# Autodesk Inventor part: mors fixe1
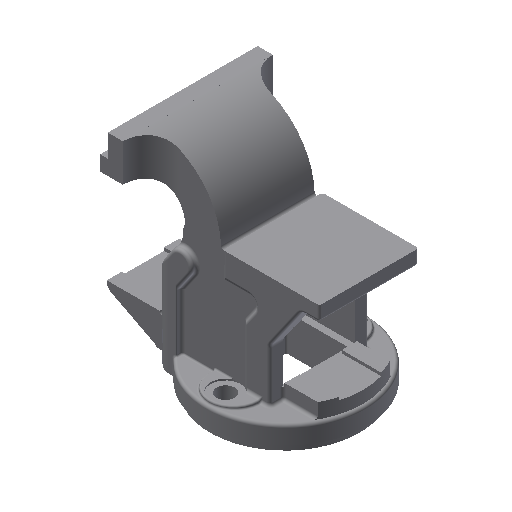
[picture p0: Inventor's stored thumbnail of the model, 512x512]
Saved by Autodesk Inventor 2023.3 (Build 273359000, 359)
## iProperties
Created: 2001-06
Part Number: mors fixe1
Material: Générique
Document SubType Name: Modélisation
Designer: Administrateur
Density: 1 g/cm^3
Appearance: Par défaut
Control State: 0
Master: False
Checked Out: False
Shininess: 21.0
Length Units: 11269
Angle Units: 11279
Time Units: 11290
Mass Units: 11283
Length Display Precision: 3
Angle Display Precision: 2
Density: 0.0
Volumn: 0.0
Area: 0.0
PropertySet Name: Model Information
Author: Administrateur
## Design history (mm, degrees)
sketch "Esquisse1"
  geometry: C1 r 53 at (19.675, 0)
  constraints: 1 centre point
  dimensions: "d0" = 106 diameter of C1
extrude "Extrusion1" new body sketch "Esquisse1" distance "d1" = 12; taper "d2" = 0 deg
fillet "Congé1" dims "d3" = 2
sketch "Esquisse2"
  geometry: C1 r 49.5 at (-0.933, -1.821)
  constraints: 1 centre point
  dimensions: "d4" = 99 diameter of C1
extrude "Extrusion2" join sketch "Esquisse2" distance "d5" = 4; taper "d6" = 0 deg
sketch "Esquisse3"
  geometry: C1 r 51 at (0, 0) reference; C2 r 16.5 at (0, 34.5); C3 r 16.5 at (0, -34.5); A1 r 34.5 centre (0, 0) between (0, 34.5) and (0, -34.5)
  constraints: 3 centre point, 2 point on circle, 1 coincident
  dimensions: "d7" = 69 diameter of A1; "d8" = 33 diameter of C3; "d9" = 33 diameter of C2
extrude "Extrusion3" join sketch "Esquisse3" distance "d10" = 2; taper "d11" = 0 deg
sketch "Esquisse5"
  geometry: L1 (54, 24)-(54, -24); L2 (45, -24)-(-95, -24); L3 (-95, -24)-(-95, 24); L4 (-95, 24)-(45, 24); C1 r 53 at (0, 0); A1 r 51 centre (0, 0) between (45, -24) and (45, 24) reference; A2 r 52 centre (0, 0) between (46.13, 24) and (-46.13, -24); 2 further points
  constraints: 8 end point, 4 point on circle, 2 centre point, 2 coincident, 2 parallel, 1 horizontal, 1 perpendicular, 1 point on line
  dimensions: "d22" = 104 diameter of A2; "d23" = 48 distance of L1.start L1.end; "d24" = 24 distance from line of L2 A1.centre; "d25" = 149 distance of L3.end L1.start; "d26" = 54 distance from line of L1 A1.centre; "d27" = 106 diameter of C1
extrude "Extrusion4" join sketch "Esquisse5" distance "d28" = 10; taper "d29" = 0 deg
sketch "Esquisse6"
  geometry: L1 (95, -24)-(45, -24) reference; L2 (95, 24)-(95, -24) reference; L3 (45, 24)-(95, 24) reference; A1 r 51 centre (0, 0) between (45, -24) and (45, 24) reference
extrude "Extrusion5" join sketch "Esquisse6" distance "d30" = 10; taper "d31" = 0 deg
sketch "Esquisse7"
  geometry: L1 (-107.728, -10)-(-107.728, 10) reference; L2 (-107.728, -10)-(-59.983, -10) reference; L3 (-59.983, -10)-(-76.775, -10); L4 (-107.728, 5.977)-(-76.775, -10); L5 (-108.465, -10)-(-107.728, 5.977)
  constraints: 6 end point, 3 point on line
extrude "Extrusion6" cut sketch "Esquisse7" extent not by distance; stored distance "d32" = 10; taper "d33" = 0 deg
fillet "Congé2" dims "d34" = 5
fillet "Congé3" dims "d35" = 5
sketch "Esquisse8"
  geometry: L1 (-95, -24)-(-95, 24) reference; L2 (-95, -14)-(56.507, -14); L3 (56.507, -14)-(56.507, 14); L4 (56.507, 14)-(-95, 14); L5 (-95, 14)-(-95, -14); A1 r 51 centre (0, 0) between (45, -24) and (45, 24) reference
  constraints: 8 end point, 2 parallel, 1 horizontal, 1 perpendicular, 1 point on line
  dimensions: "d36" = 28 distance of L4.end L2.start; "d37" = 14 distance from line of L4 A1.centre
extrude "Extrusion7" cut sketch "Esquisse8" distance "d38" = 2; taper "d39" = 0 deg
sketch "Esquisse9"
  geometry: L1 (45, -24)-(-95, -24) reference; L2 (-60, -24)-(30, -24); L3 (30, -24)-(30, 24); L4 (30, 24)-(-60, 24); L5 (-60, 24)-(-60, -24); A1 r 51 centre (0, 0) between (49.041, -14) and (49.041, 14) reference
  constraints: 8 end point, 2 parallel, 1 horizontal, 1 perpendicular, 1 point on line
  dimensions: "d40" = 90 distance of L3.end L4.end; "d41" = 48 distance of L2.end L3.end; "d42" = 30 distance from line of A1.centre L3
extrude "Extrusion8" cut sketch "Esquisse9" distance "d43" = 2; taper "d44" = 0 deg
sketch "Esquisse12"
  geometry: 1 further point
hole "Perçage2" sketch "Esquisse12" at (0, 40.133) diameter "d46" = 12; stored, may be unused: countersink angle "d50" = 60 deg, drill point angle "d52" = 118 deg; dims "d47" = 6, "d48" = 20, "d49" = 1, "d51" = 8
pattern_circular "Réseau circulaire2" dims angle "d55" = 360 deg
sketch "Esquisse13"
  geometry: L1 (75, 8)-(-15, 8) reference; L2 (32.272, 0)-(0, 0) reference; L3 (32.272, 2)-(32.272, 0) reference; L4 (57.728, 2)-(32.272, 2) reference; L5 (57.728, 0)-(57.728, 2) reference; L6 (90, 0)-(57.728, 0) reference; L7 (90, 10)-(75, 10) reference; L8 (67, 0)-(67, 35); L9 (67, 35)-(88, 65); L10 (88, 65)-(0, 65); L11 (0, 65)-(0, 0)
  constraints: 8 end point, 3 perpendicular, 1 point on line
  dimensions: "d56" = 35 distance of L8.start L8.end; "d57" = 88 distance of L9.end L10.end; "d58" = 30 distance from line of L8.end L10; "d59" = 21 horizontal distance of L9.end L8.end
extrude "Extrusion9" join sketch "Esquisse13" distance "d60" = 7; taper "d61" = 0 deg
sketch "Esquisse14"
  geometry: L1 (67, -8)-(0, -8) reference; L2 (0, -65)-(0, -8) reference; L3 (88, -65)-(0, -65) reference; L4 (67, -35)-(88, -65) reference; L5 (67, -8)-(67, -35) reference
extrude "Extrusion10" join sketch "Esquisse14" distance "d62" = 55; taper "d63" = 0 deg
sketch "Esquisse15"
  geometry: L1 (67, 0)-(0, 0) reference; L2 (67, 0)-(67, 7) reference; L3 (67, 7)-(0, 7) reference; L4 (0, 0)-(0, 7) reference
extrude "Extrusion11" join sketch "Esquisse15" distance "d64" = 10; taper "d65" = 0 deg
sketch "Esquisse16"
  geometry: L1 (88, 62)-(88, 0) reference; L2 (88, 62)-(0, 62) reference; L3 (36, 62)-(100, 62); L4 (100, 62)-(100, 0); L5 (100, 0)-(36, 0); L6 (36, 0)-(36, 62)
  constraints: 8 end point, 2 parallel, 1 horizontal, 1 perpendicular, 1 point on line
  dimensions: "d66" = 64 distance of L3.start L3.end; "d67" = 62 distance of L3.end L4.end; "d68" = 12 distance between parallel lines of L4 L1
extrude "Extrusion12" join sketch "Esquisse16" distance "d69" = 10; taper "d70" = 0 deg
sketch "Esquisse17"
  geometry: L1 (61.125, 0)-(61.125, 2) reference; L2 (67, 0)-(61.125, 0) reference; L3 (67, 35)-(67, 0) reference; L4 (88, 65)-(67, 35) reference; L5 (88, 65)-(100, 65) reference; L6 (100, 65)-(100, 75) reference; L7 (100, 75)-(36, 75) reference; L8 (61.125, 2)-(49.074, 2) reference; L9 (36, 75)-(36, 58); L10 (36, 58)-(52.746, 58); L11 (56.842, 50.133)-(50.362, 40.875); L12 (50, 39.728)-(50, 2); A1 r 5 centre (52.746, 53) between (56.842, 50.133) and (52.746, 58); A2 r 2 centre (52, 39.728) between (50.362, 40.875) and (50, 39.728); A3 r 2 centre (52, 39.728) between (50.362, 40.875) and (50, 39.728); 2 further points
  constraints: 8 end point, 7 point on line, 6 point on circle, 6 tangent, 3 centre point, 3 perpendicular, 1 parallel
  dimensions: "d71" = 17 distance of L7.end L9.end; "d72" = 17 distance between parallel lines of L4 L11; "d73" = 17 distance between parallel lines of L12 L3; "d84" = 5 radius of A1; "d85" = 2 radius of A2; "d86" = 2 radius of A3
extrude "Extrusion13" join sketch "Esquisse17" distance "d74" = 2; taper "d75" = 0 deg
fillet "Congé4" dims "d76" = 2
fillet "Congé5" dims "d77" = 2
fillet "Congé7" dims "d79" = 5
fillet "Congé8" dims "d80" = 5
fillet "Congé11" dims "d83" = 1.5
sketch "Esquisse18"
  geometry: L1 (67, 0)-(67, -33.424) reference; L2 (61.125, 0)-(67, 0) reference; L3 (61.125, -2)-(61.125, 0) reference; L4 (49.074, -2)-(61.125, -2) reference; L5 (36, -65)-(36, -75) reference; L6 (36, -75)-(100, -75) reference; L7 (100, -65)-(100, -75) reference; L8 (100, -65)-(90.603, -65) reference; L9 (67.904, -36.291)-(86.507, -62.867) reference; L10 (36, -65)-(36, -58); L11 (36, -58)-(52.746, -58); L12 (56.842, -50.133)-(50, -40.359); L13 (50, -40.359)-(50, -2); A1 r 5 centre (90.603, -60) between (86.507, -62.867) and (90.603, -65) reference; A2 r 5 centre (72, -33.424) between (67, -33.424) and (67.904, -36.291) reference; A3 r 5 centre (52.746, -53) between (52.746, -58) and (56.842, -50.133)
  constraints: 8 end point, 2 parallel, 2 perpendicular, 2 point on circle, 2 tangent, 1 centre point, 1 point on line
  dimensions: "d87" = 5 radius of A3; "d88" = 17 distance between parallel lines of L11 L6; "d89" = 17 distance between parallel lines of L12 L9; "d90" = 17 distance between parallel lines of L13 L1
extrude "Extrusion14" join sketch "Esquisse18" distance "d91" = 2; taper "d92" = 0 deg
sketch "Esquisse23"
  geometry: L1 (62.833, -24)-(49.109, -24) reference; L2 (62.833, 24)-(62.833, -24) reference; L3 (47.255, 24)-(62.833, 24) reference; A1 r 9 centre (41.261, -28.406) between (49.109, -24) and (48.01, -22.451) reference; A2 r 53 centre (0, 0) between (48.01, -22.451) and (47.255, 24) reference
extrude "Extrusion18" join sketch "Esquisse23" distance "d103" = 2; taper "d104" = 0 deg
fillet "Congé14" dims "d105" = 2
sketch "Esquisse32"
  geometry: L1 (0, -7)-(65, -7) reference; L2 (65, 55)-(65, -7) reference; L3 (65, 55)-(-2, 55) reference; L4 (-2, 55)-(-2, 52) reference; L5 (8, 48)-(0, 48) reference; L6 (8, 0)-(8, 48) reference; L7 (0, 0)-(8, 0) reference; L8 (0, 0)-(0, -7) reference
  constraints: 1 other
extrude "Extrusion27" join sketch "Esquisse32" distance "d126" = 8; taper "d127" = 0 deg
sketch "Esquisse33"
  geometry: L1 (55.642, 50.972)-(49.162, 41.715) reference; L2 (-8, 65)-(34.536, 65) reference; L3 (-8, 65)-(-8, 0) reference; L4 (-8, 65)-(-8, 47.66); L5 (7.378, 65)-(-8, 43.032); L6 (52, 39.728)-(58.48, 48.986) reference
  constraints: 4 end point, 3 point on line, 2 parallel
extrude "Extrusion28" cut sketch "Esquisse33" extent not by distance; stored distance "d128" = 10; taper "d129" = 0 deg
sketch "Esquisse34"
  geometry: L1 (-8, -43.032)-(7.378, -65) reference; L2 (56.842, -50.133)-(50, -40.359) reference; L3 (2.012, 2)-(-8, 2) reference; L4 (-8, 2)-(-8, -43.032) reference; L5 (2, 2)-(2, -31.161); L6 (2, -31.161)-(16.636, -52.07); A1 r 7.5 centre (10.492, -56.371) between (4.348, -60.671) and (16.636, -52.07)
  constraints: 4 end point, 2 parallel, 2 point on circle, 2 point on line, 1 centre point, 1 tangent
  dimensions: "d130" = 10 distance between parallel lines of L4 L5; "d131" = 15 distance between parallel lines of L1 L6
extrude "Extrusion29" join sketch "Esquisse34" distance "d133" = 4; taper "d134" = 0 deg
sketch "Esquisse35"
  geometry: L1 (67, 4)-(75, 4) reference; L2 (75, 4)-(75, 11) reference; L3 (75, 11)-(65, 11) reference; L4 (65, 7)-(65, 11) reference; L5 (64.988, 7)-(65, 7) reference; A1 r 53 centre (22, -24) between (67, 4) and (64.988, 7) reference
extrude "Extrusion30" join sketch "Esquisse35" distance "d135" = 10; taper "d136" = 0 deg
sketch "Esquisse36"
  geometry: L1 (0, 0)-(8, 0) reference; L2 (8, 10)-(8, 0) reference; L3 (8, 10)-(0, 10) reference; L4 (0, 10)-(0, 0) reference
extrude "Extrusion31" join sketch "Esquisse36" stored distance "d137" = 10; taper "d138" = 0 deg
sketch "Esquisse39"
  geometry: L1 (-4.503, -7)-(8, -7) reference; L2 (8, -7)-(8, 0) reference; L3 (0, 0)-(8, 0) reference; A1 r 51 centre (-45, 24) between (-4.503, -7) and (0, 0) reference
extrude "Extrusion33" join sketch "Esquisse39" distance "d141" = 12; taper "d142" = 0 deg
sketch "Esquisse40"
  geometry: L1 (49.109, -24)-(47.255, -24) reference; A1 r 9 centre (41.261, -28.406) between (49.109, -24) and (48.01, -22.451) reference; A2 r 53 centre (0, 0) between (47.255, -24) and (48.01, -22.451) reference
extrude "Extrusion34" join sketch "Esquisse40" distance "d143" = 2; taper "d144" = 0 deg
sketch "Esquisse41"
  geometry: L1 (7.378, 65)-(-8, 43.032) reference; L2 (-8, 43.032)-(-8, -12) reference; L3 (-8, -12)-(2.012, -12) reference; L4 (2.012, -2)-(2.012, -12) reference; L5 (7.378, 65)-(34.536, 65) reference; L6 (-8, -12)-(-8, 43.032); L7 (13.877, 61.207)-(13.877, 61.207); L8 (15.721, 50.761)-(2.012, 31.177); L9 (2.012, 31.177)-(2.012, -12); L10 (3.432, 59.363)-(-8, 43.032); L11 (-8, -12)-(2.012, -12); A1 r 7.5 centre (9.576, 55.062) between (15.721, 50.761) and (13.877, 61.207); A2 r 7.5 centre (9.576, 55.062) between (13.877, 61.207) and (3.432, 59.363)
  constraints: 12 end point, 4 point on circle, 4 tangent, 3 collinear, 2 centre point, 2 perpendicular, 1 parallel
  dimensions: "d149" = 15 distance between parallel lines of L1 L8; "d201" = 7.5 radius of A2; "d202" = 7.5 radius of A1
extrude "Extrusion35" join sketch "Esquisse41" distance "d147" = 4; taper "d148" = 0 deg
sketch "Esquisse44"
  geometry: L1 (8, 0)-(0, 0) reference; L2 (0, 0)-(0, -4) reference; L3 (5.745, -4)-(0, -4) reference; A1 r 53 centre (53, -28) between (8, 0) and (5.745, -4) reference
extrude "Extrusion36" join sketch "Esquisse44" stored distance "d154" = 4; taper "d155" = 0 deg
fillet "Congé35" dims "d173" = 10
sketch "Esquisse47"
  geometry: L1 (43.161, 4)-(0, 4) reference; L2 (0, 0)-(0, 4) reference; L3 (43.161, 0)-(0, 0) reference; L4 (43.161, 0)-(43.161, 4) reference
extrude "Extrusion39" join sketch "Esquisse47" distance "d174" = 5; taper "d175" = 0 deg
sketch "Esquisse48"
  geometry: L1 (0, -4)-(43.177, -4) reference; L2 (43.177, 0)-(43.177, -4) reference; L3 (33.177, 0)-(43.177, 0) reference; L4 (0, 0)-(33.177, 0) reference; L5 (0, 0)-(0, -4) reference
extrude "Extrusion40" join sketch "Esquisse48" distance "d176" = 5; taper "d177" = 0 deg
fillet "Congé36" dims "d182" = 2
fillet "Congé37" dims "d183" = 2
fillet "Congé38" dims "d184" = 2
fillet "Congé39" dims "d185" = 0.5
fillet "Congé40" dims "d186" = 2
fillet "Congé41" dims "d187" = 0.5
fillet "Congé42" dims "d188" = 2
fillet "Congé43" dims "d189" = 2
sketch "Esquisse51"
  geometry: L1 (5, 0.5)-(5, 2) reference; L2 (0, 4)-(7, 4) reference; L3 (0, 4)-(0, 0) reference; L4 (0, 0)-(4.5, 0) reference; A1 r 0.5 centre (4.5, 0.5) between (4.5, 0) and (5, 0.5) reference; A2 r 2 centre (7, 2) between (7, 4) and (5, 2) reference
extrude "Extrusion43" join sketch "Esquisse51" stored distance "d194" = 5; taper "d195" = 0 deg
sketch "Esquisse52"
  geometry: L1 (0, 4)-(4.5, 4) reference; L2 (0, 0)-(0, 4) reference; L3 (7, 0)-(0, 0) reference; L4 (5, 2)-(5, 3.5) reference; A1 r 0.5 centre (4.5, 3.5) between (5, 3.5) and (4.5, 4) reference; A2 r 2 centre (7, 2) between (5, 2) and (7, 0) reference
extrude "Extrusion44" join sketch "Esquisse52" stored distance "d196" = 5; taper "d197" = 0 deg
fillet "Congé50" dims "d203" = 2
fillet "Congé51" dims "d204" = 2
fillet "Congé52" dims "d205" = 2
sketch "Esquisse53"
  geometry: L1 (8, 49)-(8, -1) reference; L2 (8, 48)-(58, 48); L3 (58, 48)-(58, 0); L4 (58, 0)-(8, 0); L5 (8, 0)-(8, 48); L6 (75, 57)-(58, 57) reference
  constraints: 8 end point, 2 parallel, 1 horizontal, 1 perpendicular, 1 point on line
  dimensions: "d206" = 48 distance of L2.end L3.end; "d207" = 9 distance between parallel lines of L6 L2; "d208" = 50 distance of L2.start L2.end
extrude "Extrusion45" cut sketch "Esquisse53" distance "d209" = 91; taper "d210" = 0 deg
sketch "Esquisse55"
  geometry: L1 (10, 10)-(10, 0) reference; L2 (8, 10)-(10, 10) reference; L3 (8, 10)-(8, 0) reference; L4 (10, 0)-(8, 0) reference
extrude "Extrusion46" join sketch "Esquisse55" distance "d211" = 15; taper "d212" = 0 deg
sketch "Esquisse56"
  geometry: L1 (10, 48)-(10, 38) reference; L2 (8, 48)-(10, 48) reference; L3 (8, 48)-(8, 38) reference; L4 (10, 38)-(8, 38) reference
extrude "Extrusion47" join sketch "Esquisse56" distance "d213" = 15; taper "d214" = 0 deg
sketch "Esquisse57"
  geometry: L1 (80.522, 0)-(80.522, -48) reference; L2 (80.522, -48)-(0, -48) reference; L3 (80.522, -14)-(-14.478, -14); L4 (-14.478, -14)-(-14.478, -34); L5 (-14.478, -34)-(80.522, -34); L6 (80.522, -34)-(80.522, -14)
  constraints: 8 end point, 2 parallel, 1 horizontal, 1 perpendicular, 1 point on line
  dimensions: "d215" = 20 distance of L5.end L3.start; "d216" = 14 distance between parallel lines of L2 L5; "d217" = 95 distance of L4.end L5.end
extrude "Extrusion48" cut sketch "Esquisse57" distance "d218" = 6; taper "d219" = 0 deg
fillet "Congé53" dims "d220" = 2
sketch "Esquisse58"
  geometry: L1 (80.522, 0)-(0, 0) reference; L2 (80.522, 14)-(80.522, 0) reference; L3 (62.261, 0)-(18.261, 0); L4 (18.261, 0)-(18.261, 48); L5 (18.261, 48)-(62.261, 48); L6 (62.261, 48)-(62.261, 0)
  constraints: 8 end point, 2 parallel, 1 horizontal, 1 perpendicular, 1 point on line
  dimensions: "d221" = 48 distance of L5.end L3.start; "d222" = 44 distance of L3.start L3.end; "d223" = 18.2615 distance between parallel lines of L6 L2
extrude "Extrusion49" cut sketch "Esquisse58" distance "d224" = 8; taper "d225" = 0 deg
fillet "Congé54" dims "d226" = 5
fillet "Congé55" dims "d227" = 2
fillet "Congé56" dims "d228" = 5
fillet "Congé57" dims "d229" = 5
fillet "Congé58" dims "d230" = 2
fillet "Congé59" dims "d231" = 2
sketch "Esquisse59"
  geometry: L1 (0, 0)-(28.622, 0); L2 (28.622, 0)-(28.622, 62); L3 (28.622, 62)-(0, 62); L4 (0, 62)-(0, 0)
  constraints: 8 end point, 2 parallel, 1 horizontal, 1 perpendicular
extrude "Extrusion50" join sketch "Esquisse59" distance "d232" = 8; taper "d233" = 0 deg
fillet "Congé60" dims "d234" = 2
fillet "Congé61" dims "d235" = 2
fillet "Congé62" dims "d236" = 2
fillet "Congé63" dims "d237" = 2
fillet "Congé64" dims "d238" = 2
fillet "Congé65" dims "d239" = 10
fillet "Congé66" dims "d240" = 2
fillet "Congé67" dims "d241" = 2
fillet "Congé68" dims "d242" = 2
fillet "Congé69" dims "d243" = 1
fillet "Congé70" dims "d244" = 2
fillet "Congé71" dims "d245" = 2
fillet "Congé72" dims "d246" = 1
fillet "Congé73" dims "d247" = 1
fillet "Congé74" dims "d248" = 2
fillet "Congé75" dims "d249" = 2
fillet "Congé76" dims "d250" = 2
fillet "Congé77" dims "d251" = 1
fillet "Congé78" dims "d252" = 2
fillet "Congé79" dims "d253" = 2
fillet "Congé80" dims "d254" = 2
fillet "Congé81" dims "d255" = 2
fillet "Congé82" dims "d256" = 2
fillet "Congé83" dims "d257" = 1
fillet "Congé84" dims "d258" = 1
fillet "Congé85" dims "d259" = 1
sketch "Esquisse60"
  geometry: L1 (91, 49.857)-(75.904, 28.291) reference; L2 (28.36, 50)-(72.739, 50) reference; L3 (91, 50)-(83.452, 39.074); L4 (91, 50)-(50.55, 50); L5 (91, 50)-(48.029, 50); L6 (72.739, 38)-(82.7, 38); L7 (72.739, 38)-(72.739, 50); L8 (91, 50)-(82.7, 38)
  constraints: 12 end point, 3 point on line, 2 midpoint, 1 parallel, 1 perpendicular
  dimensions: "d260" = 12 distance of L6.start L7.end; "d261" = 0 distance from line of L2.end L7
extrude "Extrusion51" join sketch "Esquisse60" stored distance "d262" = 2; taper "d263" = 0 deg
sketch "Esquisse61"
  geometry: L1 (9.078, 48)-(26.739, 48) reference; L2 (0.362, 35.548)-(9.078, 48) reference; L3 (75, 25.424)-(75, 0) reference; L4 (26.739, 48)-(26.739, 36); L5 (26.739, 36)-(0, 34.401); L6 (9.078, 48)-(26.739, 48); A1 r 2 centre (2, 34.401) between (0.362, 35.548) and (0, 34.401) reference; 1 further point
  constraints: 6 end point, 2 perpendicular, 1 point on line
  dimensions: "d264" = 12 distance of L4.start L4.end; "d265" = 0 distance from line of point (26.739, 50) L4
extrude "Extrusion52" join sketch "Esquisse61" stored distance "d266" = 2; taper "d267" = 0 deg
sketch "Esquisse63"
  geometry: L1 (12, -48)-(0, -48) reference; L2 (0, 0)-(0, -48) reference; L3 (0, -47)-(20, -47); L4 (20, -47)-(20, -1); L5 (20, -1)-(0, -1); L6 (0, -1)-(0, -47)
  constraints: 8 end point, 2 parallel, 1 horizontal, 1 perpendicular, 1 point on line
  dimensions: "d272" = 46 distance of L3.end L4.end; "d273" = 20 distance of L3.start L3.end; "d274" = 1 distance between parallel lines of L3 L1
extrude "Extrusion54" cut sketch "Esquisse63" extent not by distance; stored distance "d275" = 2; taper "d276" = 0 deg
fillet "Congé86" dims "d277" = 1
fillet "Congé87" dims "d278" = 1
fillet "Congé88" dims "d279" = 1
sketch "Esquisse64"
  geometry: L1 (0, 0)-(-12, 0) reference; L2 (0, 47)-(-20, 47); L3 (-20, 47)-(-20, 1); L4 (-20, 1)-(0, 1); L5 (0, 1)-(0, 47); L6 (0, 39)-(0, 9) reference
  constraints: 8 end point, 2 parallel, 1 horizontal, 1 perpendicular
  dimensions: "d280" = 46 distance of L2.end L3.end; "d281" = 20 distance of L3.end L4.end; "d282" = 1 distance between parallel lines of L1 L4; "d285" = 0 distance between parallel lines of L5 L6
extrude "Extrusion55" cut sketch "Esquisse64" extent not by distance; stored distance "d283" = 2; taper "d284" = 0 deg
fillet "Congé89" dims "d286" = 1
sketch "Esquisse65"
  geometry: L1 (-53, 24)-(22, 24) reference; L2 (-23, 12.5)-(-53, 12.5); L3 (-53, 12.5)-(-53, -12.5); L4 (-53, -12.5)-(-23, -12.5); L5 (-23, -12.5)-(-23, 12.5)
  constraints: 8 end point, 2 parallel, 1 horizontal, 1 perpendicular
  dimensions: "d287" = 25 distance of L2.end L3.end; "d288" = 30 distance of L3.end L4.end; "d289" = 11.5 distance between parallel lines of L1 L2; "d290" = 0 distance from line of L3 L1.start
extrude "Extrusion56" join sketch "Esquisse65" distance "d291" = 2; taper "d292" = 0 deg
fillet "Congé90" dims "d293" = 2
sketch "Esquisse66"
  geometry: L1 (-53, 12.5)-(-23, 12.5) reference; L2 (-53, -12.5)-(-53, 12.5) reference; 1 further point
  dimensions: "d294" = 12.5 distance from line of L1 point (-33, 0); "d295" = 20 distance from line of L2 point (-33, 0)
hole "Perçage3" sketch "Esquisse66" at (-33, 0) diameter "d296" = 8; stored, may be unused: countersink angle "d300" = 60 deg, drill point angle "d302" = 118 deg; dims "d297" = 6, "d298" = 15, "d299" = 9, "d301" = 8
sketch "Esquisse68"
  geometry: L1 (-20.5, -21.5)-(-20.5, 21.5); L2 (-20.5, 21.5)-(20.5, 21.5); L3 (20.5, 21.5)-(20.5, -21.5); L4 (20.5, -21.5)-(-20.5, -21.5); C1 r 49.5 at (0, 0) reference
  constraints: 8 end point, 2 parallel, 1 perpendicular, 1 vertical
  dimensions: "d306" = 43 distance of L1.start L1.end; "d307" = 41 distance of L1.end L2.end; "d308" = 20.5 distance from line of C1.centre L1; "d309" = 21.5 distance from line of C1.centre L2
extrude "Extrusion58" cut sketch "Esquisse68" stored distance "d310" = 10; taper "d311" = 0 deg
fillet "Congé91" dims "d312" = 1
sketch "Esquisse69"
  geometry: L1 (2, 62)-(27.794, 62) reference; L2 (2, 0)-(2, 62) reference; L3 (2, 0)-(25.518, 0); L4 (25.518, 0)-(25.518, 62); L5 (25.518, 62)-(2, 62); L6 (2, 62)-(2, 0)
  constraints: 8 end point, 2 parallel, 1 horizontal, 1 perpendicular
  dimensions: "d313" = 23.51808 distance of L4.end L5.end; "d314" = 0 distance between parallel lines of L2 L6; "d315" = 0 distance between parallel lines of L1 L5
extrude "Extrusion59" join sketch "Esquisse69" distance "d316" = 48; taper "d317" = 0 deg
sketch "Esquisse70"
  geometry: L1 (0, 0)-(0, 62) reference; L2 (-48, 62)-(0, 62) reference; L3 (-48, 0)-(0, 0) reference; L4 (0, 62)-(-25, 62); L5 (-25, 62)-(-25, 0); L6 (-25, 0)-(0, 0); L7 (0, 0)-(0, 62)
  constraints: 8 end point, 2 parallel, 1 horizontal, 1 perpendicular, 1 point on line
  dimensions: "d318" = 25 distance of L5.end L6.end; "d319" = 0 distance between parallel lines of L1 L7; "d320" = 0 distance between parallel lines of L3 L6
extrude "Extrusion60" join sketch "Esquisse70" distance "d321" = 38; taper "d322" = 0 deg
fillet "Congé92" dims "d323" = 48
fillet "Congé93" dims "d324" = 23
sketch "Esquisse71"
  geometry: L1 (0, 62)-(0, 0) reference; L2 (-25, 62)-(0, 62) reference; L3 (-25, 0)-(-25, 62) reference; L4 (-25, -18.75)-(0, -18.75); L5 (0, -18.75)-(0, 80.75); L6 (0, 80.75)-(-25, 80.75); L7 (-25, 80.75)-(-25, -18.75)
  constraints: 8 end point, 2 parallel, 1 horizontal, 1 perpendicular, 1 point on line
  dimensions: "d325" = 0 distance between parallel lines of L1 L5; "d326" = 99.5 distance between parallel lines of L6 L4; "d328" = 18.75 distance between parallel lines of L6 L2
extrude "Extrusion61" join sketch "Esquisse71" distance "d329" = 15; taper "d330" = 0 deg
fillet "Congé94" dims "d331" = 18.5
fillet "Congé95" dims "d332" = 18.5
fillet "Congé96" dims "d333" = 2
fillet "Congé97" dims "d334" = 10
sketch "Esquisse73"
  geometry: L1 (0, -18.75)-(0, 80.75) reference; L2 (0, 80.75)-(-25, 80.75) reference; L3 (-25, -18.75)-(0, -18.75) reference; L4 (0, 80.75)-(-15, 80.75); L5 (-15, 80.75)-(-15, -18.75); L6 (-15, -18.75)-(0, -18.75); L7 (0, -18.75)-(0, 80.75)
  constraints: 8 end point, 2 parallel, 1 horizontal, 1 perpendicular
  dimensions: "d335" = 0 distance between parallel lines of L2 L4; "d336" = 0 distance between parallel lines of L3 L6; "d337" = 15 distance of L5.end L6.end; "d338" = 0 distance between parallel lines of L1 L7
extrude "Extrusion62" cut sketch "Esquisse73" distance "d339" = 5; taper "d340" = 0 deg
sketch "Esquisse74"
  geometry: L1 (0, -18.75)-(-15, -18.75) reference; L2 (0, 80.75)-(0, -18.75) reference; L3 (-15, 80.75)-(0, 80.75) reference; 2 further points
  dimensions: "d341" = 19.45 distance from line of L3 point (-5.25, 61.3); "d342" = 19.45 distance from line of L1 point (-5.25, 0.7); "d343" = 5.25 horizontal distance of L1.start point (-5.25, 0.7); "d344" = 5.25 distance from line of L2 point (-5.25, 61.3)
hole "Perçage4" sketch "Esquisse74" at (-5.25, 61.3), (-5.25, 0.7) diameter "d345" = 4.134; stored, may be unused: countersink angle "d349" = 60 deg, drill point angle "d351" = 118 deg; dims "d346" = 10, "d347" = 4, "d348" = 2, "d350" = 13.2
hole "Perçage5" diameter "d354" = 15; stored, may be unused: countersink angle "d358" = 90 deg, drill point angle "d360" = 0 deg; dims "d355" = 6, "d356" = 4, "d357" = 2, "d359" = 6, "d361" = 10, "d362" = 10
node "Solide1"
node "Corps solides"
node "Corps surfaciques"
